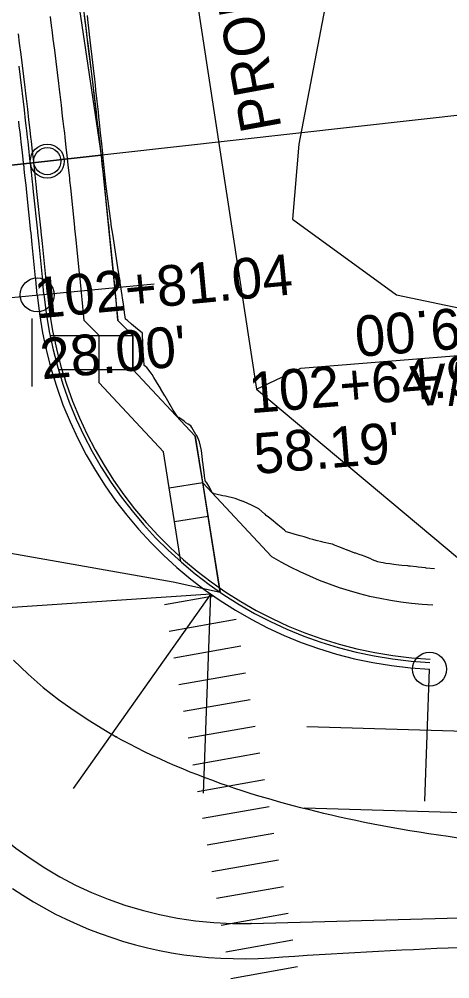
# Model space of a CAD drawing. Extents: x -70 to 701944, y -4 to 666871.
# Drawn here: x 668432 to 668495.4, y 653448.4 to 653589.9 of the extents above; entities that cross this region are included whole.
import ezdxf

# ---------------------------------------------------------------- set-up
doc = ezdxf.new("R2010")
doc.units = 0
for name, color, linetype in [('R_Detour', 7, 'Continuous'), ('R_Draft', 7, 'Continuous'), ('R_Horz Alg', 7, 'Continuous'), ('R_No Plot', 7, 'Continuous'), ('R_Proposed Const Limits', 7, 'Continuous'), ('R_Proposed Road', 7, 'Continuous'), ('R_ROW', 7, 'Continuous'), ('R_ROW Annot', 7, 'Continuous'), ('R_Striping', 7, 'Continuous'), ('R_Water', 7, 'Continuous'), ('T_Drafting', 7, 'Continuous'), ('T_Vehicle Path Lt Major', 7, 'Continuous')]:
    doc.layers.add(name, color=color, linetype=linetype)

msp = doc.modelspace()

# ---------------------------------------------------------------- linework, layer by layer
at = {"layer": 'R_Detour'}
msp.add_line((668533.12, 653579.75), (668404.81, 653565.44), dxfattribs=at)
at = {"layer": 'R_Draft'}
for p, q in [((668406.75, 653546.58), (668451.88, 653550.86)), ((668410.19, 653501.8), (668460.19, 653505.14)), ((668460.19, 653505.14), (668439.95, 653476.45)), ((668459.14, 653475.77), (668460.19, 653505.14)), ((668491.74, 653474.61), (668492.43, 653494.05))]:
    msp.add_line(p, q, dxfattribs=at)
at = {"layer": 'R_Horz Alg'}
for centre in [(668434.63, 653549.23), (668492.43, 653494.05)]:
    msp.add_circle(centre, 2.5, dxfattribs=at)
msp.add_arc((668495.36, 653554.98), 61, 185.4143, 267.2525, dxfattribs=at)
at = {"layer": 'R_No Plot'}
for points in [[(668392.45, 653648.51), (668431.29, 653655.75), (668444.07, 653569.82), (668404.81, 653565.44)], [(668405.56, 653558.49), (668404.81, 653565.44), (668444.07, 653569.82), (668446.53, 653545.45), (668448.74, 653543.24), (668448.74, 653538.24), (668457.92, 653528.41), (668461.59, 653505.38), (668454.67, 653506.87), (668409.31, 653514.88)]]:
    msp.add_lwpolyline(points, close=True, dxfattribs=at)
msp.add_circle((668436.12, 653568.94), 2.5, dxfattribs=at)
at = {"layer": 'R_Proposed Const Limits'}
for points in [[(668446.96, 653550.4), (668446.61, 653552.68), (668446.57, 653552.94), (668445.81, 653557.87), (668445.54, 653559.57), (668445.52, 653559.65), (668445.51, 653559.75), (668444.75, 653565.57), (668444.64, 653566.64), (668444.6, 653567.03), (668444.45, 653568.51), (668444.31, 653569.85), (668444.29, 653570.01), (668444.13, 653571.53), (668443.97, 653573.07), (668443.91, 653573.65), (668443.91, 653573.67), (668443.81, 653574.63), (668443.72, 653575.46), (668443.64, 653576.2), (668443.47, 653577.79), (668443.29, 653579.4), (668443.21, 653580.14), (668443.15, 653580.65), (668443.11, 653581.02), (668442.93, 653582.65), (668442.74, 653584.3), (668442.55, 653585.95), (668442.36, 653587.62), (668442.35, 653587.65), (668442.19, 653589), (668442.16, 653589.3), (668442.03, 653590.42)], [(668455.36, 653531.22), (668454.67, 653532.22), (668454.21, 653533.02), (668454.07, 653533.27), (668453.46, 653534.32), (668453.44, 653534.35), (668452.86, 653535.33), (668452.84, 653535.37), (668452.21, 653536.43), (668451.82, 653537.07), (668451.57, 653537.48), (668451.44, 653537.68), (668450.8, 653538.5), (668450.4, 653538.84), (668450.39, 653538.84), (668450.39, 653538.86), (668450.34, 653539.65), (668450.26, 653540.92), (668450.23, 653541.35), (668450.2, 653541.84), (668450.18, 653542.11), (668450.17, 653542.17), (668450.13, 653543.42), (668450.13, 653543.59), (668449.12, 653544.43), (668448.52, 653544.93), (668447.91, 653545.44), (668447.64, 653545.67), (668447.5, 653546.65), (668447.33, 653547.9), (668447.21, 653548.72), (668447.15, 653549.15), (668446.96, 653550.39)], [(668460.42, 653520.06), (668460.06, 653520.78), (668459.63, 653521.54), (668459.38, 653521.84), (668459.37, 653521.88), (668459.32, 653522.27), (668459.3, 653522.44), (668459.28, 653522.65), (668459.18, 653523.39), (668459.08, 653524.23), (668459, 653524.86), (668458.98, 653524.96), (668458.82, 653526.28), (668458.55, 653527.59), (668458.19, 653528.38), (668458.12, 653528.55), (668458.01, 653528.66), (668457.43, 653529.7), (668457.25, 653529.91), (668456.85, 653530.19), (668456.55, 653530.39), (668456.44, 653530.47), (668456.27, 653530.59), (668455.5, 653531.13), (668455.36, 653531.22)], [(668493.14, 653508.86), (668491.95, 653508.96), (668491.83, 653508.97), (668490.76, 653509.1), (668490.52, 653509.13), (668489.57, 653509.25), (668489.38, 653509.26), (668489.21, 653509.28), (668488.37, 653509.35), (668487.89, 653509.4), (668487.18, 653509.48), (668486.58, 653509.56), (668485.99, 653509.65), (668485.62, 653509.71), (668485.27, 653509.77), (668484.8, 653509.86), (668484.01, 653510.18), (668483.69, 653510.36), (668482.8, 653510.73), (668482.57, 653510.8), (668482.04, 653510.98), (668481.55, 653511.14), (668481.44, 653511.18), (668480.32, 653511.59), (668480.31, 653511.59), (668479.21, 653512.03), (668479.09, 653512.07), (668478.52, 653512.31), (668478.11, 653512.48), (668477.86, 653512.53), (668476.92, 653512.75), (668476.56, 653512.84), (668475.74, 653513.04), (668475.26, 653513.17), (668474.81, 653513.29), (668474.56, 653513.36), (668473.96, 653513.54), (668473.38, 653513.72), (668472.65, 653513.93), (668472.18, 653514.06), (668471.33, 653514.32), (668471.11, 653514.5), (668471.05, 653514.55), (668470.09, 653515.34), (668469.14, 653516.11), (668468.69, 653516.47), (668468.37, 653516.73), (668468.2, 653516.88), (668468.11, 653516.96), (668468.1, 653516.97), (668467.29, 653517.69), (668466.18, 653518.25), (668465.13, 653518.7), (668465.01, 653518.75), (668464.96, 653518.78), (668464.84, 653518.82), (668464.72, 653518.88), (668464.7, 653518.88), (668463.8, 653519.23), (668462.39, 653519.54), (668461.99, 653519.62), (668460.93, 653519.84), (668460.65, 653519.9), (668460.42, 653520.06)]]:
    msp.add_lwpolyline(points, dxfattribs=at)
at = {"layer": 'R_Proposed Road'}
for p, q in [((668441.5, 653545.48), (668443.74, 653543.24)), ((668448.74, 653543.24), (668446.53, 653545.45)), ((668436.52, 653543.24), (668443.74, 653543.24)), ((668443.74, 653543.24), (668448.74, 653543.24)), ((668443.74, 653536.27), (668443.74, 653543.24)), ((668448.74, 653538.24), (668448.74, 653543.24)), ((668437.74, 653538.24), (668443.74, 653538.24)), ((668443.74, 653538.24), (668448.74, 653538.24)), ((668457.92, 653528.41), (668448.74, 653538.24)), ((668443.74, 653536.27), (668453.22, 653526.11)), ((668459.02, 653521.51), (668457.92, 653528.41)), ((668455.81, 653509.86), (668453.22, 653526.11)), ((668459.02, 653521.51), (668454.08, 653520.72)), ((668461.59, 653505.38), (668459.02, 653521.51)), ((668469.15, 653510.65), (668459.02, 653521.51)), ((668459.81, 653516.57), (668454.87, 653515.78))]:
    msp.add_line(p, q, dxfattribs=at)
for points in [[(668441.53, 653545.45), (668440.89, 653552.13), (668440.87, 653552.39), (668440.38, 653557.32), (668440.2, 653559.03), (668440.19, 653559.11), (668440.18, 653559.2), (668439.57, 653565.01), (668439.46, 653566.08), (668439.42, 653566.46), (668439.25, 653567.94), (668439.11, 653569.27), (668439.09, 653569.43), (668438.92, 653570.94), (668438.74, 653572.47), (668438.68, 653573.05), (668438.68, 653573.07), (668438.57, 653574.02), (668438.47, 653574.85), (668438.38, 653575.59), (668438.2, 653577.17), (668438.01, 653578.77), (668437.92, 653579.5), (668437.86, 653580.01), (668437.81, 653580.38), (668437.62, 653582), (668437.41, 653583.64), (668437.21, 653585.28), (668437, 653586.94), (668437, 653586.97), (668436.83, 653588.31), (668436.79, 653588.61), (668436.64, 653589.72), (668436.57, 653590.28)], [(668446.09, 653550.31), (668445.87, 653552.61), (668445.84, 653552.87), (668445.35, 653557.83), (668445.18, 653559.54), (668445.17, 653559.62), (668445.16, 653559.71), (668444.54, 653565.55), (668444.43, 653566.62), (668444.39, 653567), (668444.22, 653568.48), (668444.08, 653569.82), (668444.06, 653569.98), (668443.89, 653571.5), (668443.71, 653573.04), (668443.65, 653573.62), (668443.64, 653573.64), (668443.53, 653574.6), (668443.44, 653575.42), (668443.35, 653576.17), (668443.16, 653577.76), (668442.97, 653579.36), (668442.88, 653580.1), (668442.82, 653580.61), (668442.78, 653580.98), (668442.58, 653582.61), (668442.38, 653584.25), (668442.17, 653585.9), (668441.96, 653587.57), (668441.96, 653587.6), (668441.79, 653588.95), (668441.75, 653589.24), (668441.6, 653590.36)], [(668436.13, 653549.37), (668435.91, 653551.65), (668435.89, 653551.91), (668435.4, 653556.82), (668435.23, 653558.52), (668435.22, 653558.59), (668435.21, 653558.69), (668434.6, 653564.47), (668434.49, 653565.54), (668434.45, 653565.92), (668434.28, 653567.39), (668434.14, 653568.71), (668434.12, 653568.87), (668433.95, 653570.38), (668433.78, 653571.9), (668433.71, 653572.48), (668433.71, 653572.5), (668433.6, 653573.45), (668433.5, 653574.27), (668433.42, 653575.01), (668433.23, 653576.58), (668433.04, 653578.17), (668432.96, 653578.9), (668432.89, 653579.41), (668432.85, 653579.77), (668432.65, 653581.39), (668432.45, 653583.02), (668432.25, 653584.66), (668432.04, 653586.31), (668432.04, 653586.34), (668431.87, 653587.68)], [(668435.63, 653549.32), (668435.42, 653551.6), (668435.39, 653551.86), (668434.9, 653556.77), (668434.73, 653558.46), (668434.72, 653558.54), (668434.71, 653558.64), (668434.1, 653564.42), (668433.99, 653565.48), (668433.95, 653565.87), (668433.79, 653567.33), (668433.64, 653568.66), (668433.62, 653568.82), (668433.45, 653570.32), (668433.28, 653571.85), (668433.21, 653572.42), (668433.21, 653572.45), (668433.1, 653573.39), (668433.01, 653574.21), (668432.92, 653574.95), (668432.74, 653576.52), (668432.55, 653578.11), (668432.46, 653578.84), (668432.4, 653579.35), (668432.35, 653579.71), (668432.16, 653581.33), (668431.96, 653582.96)], [(668434.63, 653549.17), (668434.63, 653549.23), (668434.41, 653551.5), (668434.39, 653551.76), (668433.9, 653556.67), (668433.73, 653558.36), (668433.72, 653558.44), (668433.71, 653558.54), (668433.1, 653564.31), (668432.99, 653565.38), (668432.94, 653565.76), (668432.78, 653567.22), (668432.64, 653568.55), (668432.62, 653568.71), (668432.45, 653570.21), (668432.28, 653571.73), (668432.21, 653572.31), (668432.21, 653572.33), (668432.1, 653573.27), (668432, 653574.09), (668431.92, 653574.83)]]:
    msp.add_lwpolyline(points, dxfattribs=at)
for centre, radius, start, end in [((667265.95, 653438.46), 1185.42, 5.41427, 8.36232), ((667265.95, 653438.46), 1185.42, 5.17856, 5.41427), ((668495.36, 653554.98), 61, 185.4143, 267.2525), ((668495.36, 653554.98), 60, 185.4143, 267.2525), ((668495.36, 653554.98), 59.5, 185.4143, 267.2525), ((668495.36, 653554.98), 51.5, 239.4174, 267.2525)]:
    msp.add_arc(centre, radius, start, end, dxfattribs=at)
at = {"layer": 'R_ROW'}
msp.add_lwpolyline([(668379.35, 655858.1), (668375.98, 655777.07), (668370.36, 655679.23), (668386.89, 655520.28), (668407.12, 655376.16), (668401.28, 655337.39), (668367.53, 655300.94), (668336.13, 654741.8), (668319.02, 654252.06), (668346.25, 654066.79), (668364.92, 653986.53), (668401.01, 653983.18), (668425.78, 653872.16), (668398.63, 653868.03), (668433.79, 653730.98), (668450.99, 653639.16), (668466.96, 653535.35), (668502.13, 653505.82)], dxfattribs=at)
at = {"layer": 'R_ROW Annot'}
msp.add_lwpolyline([(668466.96, 653535.35), (668473.46, 653538.41), (668554.55, 653544.95)], dxfattribs=at)
at = {"layer": 'R_Striping'}
for p, q in [((668433.83, 653545.74), (668433.83, 653535.74)), ((668460.61, 653504.84), (668453.39, 653503.56)), ((668463.93, 653501.37), (668454.08, 653499.62)), ((668464.63, 653497.43), (668454.78, 653495.69)), ((668465.32, 653493.49), (668455.48, 653491.75)), ((668466.02, 653489.55), (668456.17, 653487.81)), ((668466.72, 653485.61), (668456.87, 653483.87)), ((668467.41, 653481.67), (668457.57, 653479.93)), ((668468.11, 653477.73), (668458.26, 653475.99)), ((668468.81, 653473.79), (668458.96, 653472.05)), ((668469.5, 653469.86), (668459.65, 653468.11)), ((668470.2, 653465.92), (668460.35, 653464.17)), ((668470.9, 653461.98), (668461.05, 653460.24)), ((668471.59, 653458.04), (668461.74, 653456.3)), ((668472.29, 653454.1), (668462.44, 653452.36)), ((668472.98, 653450.16), (668463.14, 653448.42))]:
    msp.add_line(p, q, dxfattribs=at)
at = {"layer": 'R_Water'}
msp.add_circle((668436.12, 653568.94), 2, dxfattribs=at)
at = {"layer": 'T_Drafting'}
msp.add_lwpolyline([(668422.16, 653785.25), (668432.31, 653772.29), (668436.33, 653765.81), (668435.11, 653761.78), (668434.42, 653751.83), (668443.45, 653689.73), (668447.13, 653670.11), (668447.13, 653670.11), (668462.45, 653663.06), (668470.41, 653656.93), (668472.25, 653652.03), (668476.84, 653622.3), (668478.07, 653597.17), (668473.17, 653571.43), (668472.25, 653560.39), (668487.54, 653549.24), (668510.55, 653544.44), (668527.49, 653553.75), (668549.2, 653563.7), (668579.18, 653601.19)], dxfattribs=at)
at = {"layer": 'T_Vehicle Path Lt Major'}
msp.add_line((668466.14, 653456.59), (668565.53, 653459.31), dxfattribs=at)
for points in [[(668474.34, 653485.62), (668489.33, 653485.16), (668504.33, 653484.71), (668519.23, 653484.25), (668534.13, 653484.03), (668549.01, 653483.81), (668562.97, 653483.88), (668576.08, 653485.98), (668589.34, 653489.93), (668601.97, 653494.59), (668613.86, 653501.81), (668627.16, 653509.67), (668641.34, 653516.87), (668655.98, 653522.79), (668670.41, 653527.85), (668684.58, 653532.8), (668698.86, 653537.77), (668713.21, 653542.46), (668727.43, 653547.14), (668741.61, 653551.88), (668755.84, 653556.69), (668770.1, 653561.41), (668784.33, 653566.14)], [(668473.98, 653473.62), (668488.97, 653473.17), (668503.96, 653472.72), (668518.95, 653472.25), (668533.95, 653472.03), (668548.95, 653471.81), (668563.95, 653471.88), (668578.76, 653474.25), (668593.13, 653478.54), (668607.21, 653483.73), (668620.03, 653491.51), (668632.94, 653499.14), (668646.31, 653505.94), (668660.22, 653511.56), (668674.37, 653516.53), (668688.53, 653521.47), (668702.7, 653526.4), (668716.95, 653531.06), (668731.2, 653535.75), (668745.43, 653540.5), (668759.64, 653545.31), (668773.88, 653550.02), (668788.11, 653554.75)], [(668431.12, 653495.39), (668433.3, 653493.31), (668435.53, 653491.38), (668437.79, 653489.59), (668440.07, 653487.95), (668442.37, 653486.42), (668444.67, 653485.01), (668446.28, 653484.09)], [(668446.28, 653484.09), (668446.97, 653483.71), (668448.12, 653483.09), (668449.26, 653482.5), (668450.39, 653481.94), (668451.52, 653481.39), (668452.66, 653480.87), (668453.78, 653480.36), (668454.91, 653479.87), (668456.03, 653479.4), (668457.14, 653478.94), (668458.25, 653478.51), (668459.35, 653478.08), (668460.44, 653477.68), (668461.54, 653477.28), (668462.62, 653476.9), (668463.7, 653476.54), (668464.77, 653476.19), (668465.83, 653475.84), (668466.89, 653475.51), (668467.96, 653475.19), (668469.03, 653474.88), (668470.11, 653474.57), (668471.19, 653474.27), (668472.31, 653473.97), (668473.41, 653473.68), (668474.53, 653473.4), (668475.67, 653473.12), (668476.81, 653472.84), (668477.97, 653472.57), (668479.14, 653472.31), (668480.36, 653472.05), (668481.59, 653471.79), (668482.85, 653471.53), (668484.13, 653471.28), (668485.45, 653471.02), (668486.78, 653470.78), (668488.13, 653470.54), (668489.51, 653470.3), (668490.9, 653470.07), (668492.31, 653469.85), (668493.74, 653469.63), (668495.18, 653469.42), (668496.63, 653469.21)], [(668431.01, 653461.72), (668432.53, 653460.73), (668434.07, 653459.78), (668435.65, 653458.87), (668437.25, 653458.02), (668438.88, 653457.21), (668440.53, 653456.45), (668442.2, 653455.75), (668443.9, 653455.09), (668445.62, 653454.49), (668447.35, 653453.93), (668449.1, 653453.43), (668450.87, 653452.99), (668452.65, 653452.6), (668454.44, 653452.26), (668456.24, 653451.97), (668458.05, 653451.75), (668459.87, 653451.57), (668461.69, 653451.45), (668463.51, 653451.39), (668465.34, 653451.38), (668467.16, 653451.43), (668468.99, 653451.53), (668470.8, 653451.65), (668472.59, 653451.77), (668474.38, 653451.88), (668476.15, 653451.99), (668477.92, 653452.1), (668479.67, 653452.2), (668481.42, 653452.3), (668483.16, 653452.4), (668484.89, 653452.5), (668486.62, 653452.59), (668488.34, 653452.68), (668490.06, 653452.76), (668491.78, 653452.85), (668493.48, 653452.93), (668495.18, 653452.98), (668496.86, 653453.01)]]:
    msp.add_lwpolyline(points, dxfattribs=at)
for centre in [(668446.28, 653484.09), (668446.28, 653484.09), (668466.14, 653456.59), (668466.14, 653456.59)]:
    msp.add_circle(centre, 0.0417, dxfattribs=at)
msp.add_arc((668464.64, 653511.57), 55, 183.4903, 271.5679, dxfattribs=at)

# ---------------------------------------------------------------- texts
at = {"layer": 'R_No Plot'}
for s, rotation, p in [('102+81.04 ', 5.4142, (668434.49, 653545.72)), ("28.00' ", 5.4142, (668435.34, 653536.76)), ('102+64.99 ', 4.6116, (668466.04, 653531.77)), ("58.19' ", 4.6116, (668466.76, 653522.8))]:
    msp.add_text(s, height=6, rotation=rotation, dxfattribs=at).set_placement(p)
at = {"layer": 'R_ROW'}
msp.add_text('PROP. R/W ', height=6, rotation=100.4307, dxfattribs=at).set_placement((668470.65, 653573.85))
at = {"layer": 'R_ROW Annot'}
for s, p in [('59.00', (668501.22, 653547.67)), ('+65.00 BEGIN C/A', (668556.75, 653544.13))]:
    msp.add_text(s, height=6, rotation=184.6122, dxfattribs=at).set_placement(p)

doc.saveas('drawing.dxf')
